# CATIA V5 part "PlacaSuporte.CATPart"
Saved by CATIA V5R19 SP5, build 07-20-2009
Part number: PlacaSuporte
Bounding box of the stored display mesh (mm): x -35 to 35, y 0 to 8, z -42.5 to 37.5
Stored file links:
  Z:\UA\ATLAS\atlascar\ServoPiloto\dir\suportePotenciometro\V2\PlacaSuporte.CATPart
  Z:\UA\ATLAS\atlascar\ServoPiloto\dir\suportePotenciometro\V2\potenciometro\TampaSuporteRolamentos.CATPart
  Z:\programs_vbox\Dassault Systemes\B19\intel_a\reffiles\standard\MetricThickPitch.txt
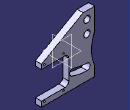
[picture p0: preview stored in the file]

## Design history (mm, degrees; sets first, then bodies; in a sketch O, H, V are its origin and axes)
Body1 (main body)
  Sketch1 on zx-plane, origin (0, 0, 0), H (-1, 0, 0), V (0, 0, 1)
    line L1 (-35, 37.5) -> (35, 37.5)
    line L2 (35, 37.5) -> (35, -42.5)
    line L3 (35, -42.5) -> (-35, -42.5)
    line L4 (-35, -42.5) -> (-35, 37.5)
    circle A1 centre (25, 27.5) radius 4.25
    point P5 (25, 27.5)
    construction arc A2 centre (25, 27.5) radius 54 from (6.5309, -23.2434) to (25, -26.5) ccw
    point P6 (6.5309, -23.2434)
    point P7 (25, -26.5)
    arc A3 centre (6.5309, -23.2434) radius 4.25 from (5.0773, -27.2371) to (7.9845, -19.2497) cw
    arc A4 centre (25, -26.5) radius 4.25 from (25, -22.25) to (25, -30.75) cw
    arc A5 centre (25, 27.5) radius 49.75 from (7.9845, -19.2497) to (25, -22.25) ccw
    arc A6 centre (25, 27.5) radius 58.25 from (25, -30.75) to (5.0773, -27.2371) cw
    construction line L5 (25, 27.5) -> (25, -95.7931)
    construction line L6 (25, 27.5) -> (-16.0239, -85.2122)
    circle A7 centre (-20, -17.5) radius 9
    point P14 (-20, -17.5)
    construction line L7 (-53.4291, -17.5) -> (31.7206, -17.5)
    axis line L8 (-20, 27.4739) -> (-20, -70.0577)
    circle A8 centre (25, 11.085) radius 4.25
    point P19 (25, 11.085)
    construction circle A9 centre (25, 27.5) radius 16.415
    radius A1 = 4.25
    distance L2 V = 35 {= deleted_LENGTH /2}
    distance L1 H = 37.5 {= deleted_LENGTH /2}
    radius A4 = 4.25
    angle L5 L6 = 20
    radius A2 = 54
    distance P5 L1 = 10
    distance P5 L2 = 10
    radius A7 = 9
    distance L8 L2 = 55
    distance L1 L3 = 80
    distance L7 L1 = 55
    distance L2 L4 = 70
    radius A8 = 4.25 {= Sketch1.radius(A1)}
    radius A9 = 16.415
    horizontal: L1 H, L3 H, L7 H
    vertical: L2 V, L4 V, L5 V, L8 V
    tangency: A5 A4, A4 A6, A6 A3, A3 A5
    concentricity: A5 P5, A6 P5
    coincidence: L5 P7, L6 P6, P14 L8, P14 L7, P19 L5, P19 A9
  Pad1: profile Sketch1, direction (0, 1, 0), length 8
  Sketch2 on end face of Pad1, origin (0, 8, 0), H (-1, 0, 0), V (0, 0, 1)
    arc A1 centre (76.3479, -10.3294) radius 45.584 from (35, 8.8604) to (35, -29.5192) ccw
    point P2 (35, 8.8604)
    point P3 (35, -29.5192)
    reference projected line E1 (35, -37.5) -> (35, 37.5) from edge [face of Pad1 from Sketch1.L2 | end face of Pad1]
    reference projected line E2 (35, -37.5) -> (35, 37.5) from edge [face of Pad1 from Sketch1.L2 | end face of Pad1]
    reference projected arc E3 centre (25, -26.5) radius 4.25 from (25, -30.75) to (25, -22.25) ccw from edge [end face of Pad1 | face of Pad1 from Sketch1.A4]
    distance A1 E3 = 4
    coincidence: P2 E1, E2 P3
  Pocket1: profile Sketch2, direction (0, -1, 0), through (limit type 6)
  Sketch3 on start face of Pad1, origin (0, 0, 0), H (1, 0, 0), V (0, 0, 1)
    line L1 (-1, 0.5) -> (35, 0.5)
    line L2 (35, 0.5) -> (35, -35.5)
    line L3 (35, -35.5) -> (-1, -35.5)
    line L4 (-1, -35.5) -> (-1, 0.5)
    axis line L5 (-2.3607, -17.5) -> (81.8178, -17.5)
    point P7 (20, -17.5)
    reference projected circle E1 centre (20, -17.5) radius 9 from edge [face of Pad1 from Sketch1.A7 | start face of Pad1]
    reference projected line E2 (35, 37.5) -> (35, -37.5) from edge [start face of Pad1 | face of Pad1 from Sketch1.L4]
    projected line E3 (35, 37.5) -> (35, -42.5) from edge [start face of Pad1 | face of Pad1 from Sketch1.L4]
    projected line E4 (35, 37.5) -> (35, 6.5) from edge [start face of Pad1 | face of Pad1 from Sketch1.L4]
    projected line E5 (-35, 37.5) -> (35, 37.5) from edge [start face of Pad1 | face of Pad1 from Sketch1.L1]
    projected line E6 (-20, 37.5) -> (35, 37.5) from edge [start face of Pad1 | face of Pad1 from Sketch1.L1]
    line L6 (35, 6.5) -> (-20, 37.5)
    point P12 (35, 6.5)
    point P13 (-20, 37.5)
    reference projected line E7 (-35, -47.5) -> (-35, 37.5) from edge [start face of Pad1 | face of Pad1 from Sketch1.L2]
    distance L1 L3 = 36
    distance L2 L4 = 36
    distance L5 L1 = 18 {= Sketch3.distance(L1 L3) /2}
    distance L1 P12 = 6
    distance E7 P13 = 15
    horizontal: L1 H, L3 H, L5 H
    vertical: L2 V, L4 V
    concentricity: P7 E1
    coincidence: L5 P7, L2 E2, P12 E3, P13 E5
  Pocket2: profile Sketch3, direction (0, 1, 0), through (limit type 3)
  Sketch4 on start face of Pad1, origin (0, 0, 0), H (1, 0, 0), V (0, 0, 1)
    construction line L1 (-3.9447, 4) -> (40.2648, 4)
    circle A1 centre (6, 4) radius 1.25
    point P3 (6, 4)
    circle A2 centre (31, 4) radius 1.25
    point P4 (31, 4)
    reference projected line E1 (35, 0.5) -> (2, 0.5) from edge [start face of Pad1 | face of Pocket2 from Sketch3.L1]
    axis line L2 (-5.8297, -17) -> (49.4075, -17)
    reference projected line E2 (35, 0.5) -> (2, 0.5) from edge [start face of Pad1 | face of Pocket2 from Sketch3.L1]
    reference projected line E3 (2, -35.5) -> (35, -35.5) from edge [start face of Pad1 | face of Pocket2 from Sketch3.L3]
    reference projected line E4 (35, 0.5) -> (2, 0.5) from edge [start face of Pad1 | face of Pocket2 from Sketch3.L1]
    circle A3 centre (31, -38) radius 1.25
    circle A4 centre (6, -38) radius 1.25
    reference projected line E5 (35, 37.5) -> (35, -47.5) from edge [start face of Pad1 | face of Pad1 from Sketch1.L4]
    radius A1 = 1.25
    radius A2 = 1.25 {= Sketch4.radius(A1)}
    distance A1 A2 = 25
    distance L1 E1 = 3.5
    distance E2 E3 = 36 (reference)
    distance E4 L2 = 17.5
    distance P4 E5 = 4
    horizontal: L1 H, L2 H
    coincidence: P3 L1, P4 L1
    symmetry: A2 A3 L2, A1 A4 L2
  Pocket3: profile Sketch4, direction (0, 1, 0), through (limit type 3)
  Thread1: "M3", diameter 3, depth 8, pitch 0.5, on face of Pocket3 from Sketch4.A1, from start face of Pad1
  Thread2: "M3", diameter 3, depth 8, pitch 0.5, on face of Pocket3 from Sketch4.A4, from start face of Pad1
  Thread3: "M3", diameter 3, depth 8, pitch 0.5, on face of Pocket3 from Sketch4.A3, from start face of Pad1
  Thread4: "M3", diameter 3, depth 8, pitch 0.5, on face of Pocket3 from Sketch4.A2, from start face of Pad1
  Fillet1: radius 5, on edge [face of Pocket2 from Sketch3.L3 | face of Pocket2 from Sketch3.L4]; edge [face of Pocket2 from Sketch3.L4 | face of Pocket2 from Sketch3.L1]
Relations
  Sketch4.distance(E4 L2) = Sketch4.distance(E2 E3) / 2 (deactivated)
